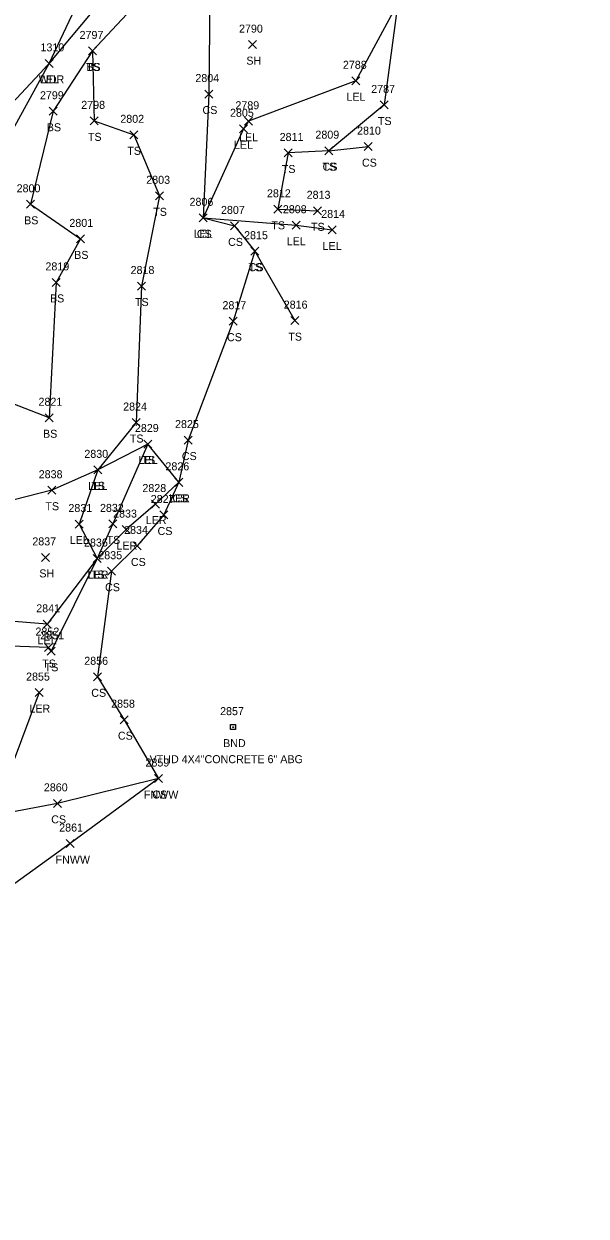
# Model space of a CAD drawing. Extents: x 1483143 to 1488182, y 802902 to 807581.
# Drawn here: x 1487452.4 to 1487593, y 805194.3 to 805492.2 of the extents above; entities that cross this region are included whole.
import ezdxf

# ---------------------------------------------------------------- set-up
doc = ezdxf.new("R2010")
doc.units = 0
for name, color, linetype in [('L_A', 7, 'Continuous'), ('L_I', 7, 'Continuous'), ('L_TIC', 7, 'Continuous'), ('LARO', 7, 'Continuous'), ('LAWA', 7, 'Continuous'), ('LELB', 7, 'Continuous'), ('LFNC', 7, 'Continuous'), ('M_A', 7, 'Continuous'), ('M_C', 7, 'Continuous'), ('M_I', 7, 'Continuous'), ('MHBP', 7, 'Continuous')]:
    doc.layers.add(name, color=color, linetype=linetype)

msp = doc.modelspace()

# ---------------------------------------------------------------- linework, layer by layer
at = {"layer": 'L_TIC'}
for points in [[(1487508.55, 805486.02), (1487510.55, 805488.02)], [(1487510.55, 805486.02), (1487508.55, 805488.02)], [(1487468.62, 805484.44), (1487470.62, 805486.44)], [(1487470.62, 805484.44), (1487468.62, 805486.44)], [(1487468.62, 805484.44), (1487470.62, 805486.44)], [(1487470.62, 805484.44), (1487468.62, 805486.44)], [(1487457.8, 805481.34), (1487459.8, 805483.34)], [(1487459.8, 805481.34), (1487457.8, 805483.34)], [(1487457.8, 805481.34), (1487459.8, 805483.34)], [(1487459.8, 805481.34), (1487457.8, 805483.34)], [(1487534.43, 805476.98), (1487536.43, 805478.98)], [(1487536.43, 805476.98), (1487534.43, 805478.98)], [(1487497.64, 805473.67), (1487499.64, 805475.67)], [(1487499.64, 805473.67), (1487497.64, 805475.67)], [(1487541.5, 805470.94), (1487543.5, 805472.94)], [(1487543.5, 805470.94), (1487541.5, 805472.94)], [(1487458.73, 805469.37), (1487460.73, 805471.37)], [(1487460.73, 805469.37), (1487458.73, 805471.37)], [(1487469.04, 805466.97), (1487471.04, 805468.97)], [(1487471.04, 805466.97), (1487469.04, 805468.97)], [(1487506.3, 805464.99), (1487508.3, 805466.99)], [(1487508.3, 805464.99), (1487506.3, 805466.99)], [(1487507.57, 805466.87), (1487509.57, 805468.87)], [(1487509.57, 805466.87), (1487507.57, 805468.87)], [(1487478.88, 805463.48), (1487480.88, 805465.48)], [(1487480.88, 805463.48), (1487478.88, 805465.48)], [(1487517.49, 805458.95), (1487519.49, 805460.95)], [(1487519.49, 805458.95), (1487517.49, 805460.95)], [(1487527.65, 805459.52), (1487529.65, 805461.52)], [(1487529.65, 805459.52), (1487527.65, 805461.52)], [(1487527.65, 805459.52), (1487529.65, 805461.52)], [(1487529.65, 805459.52), (1487527.65, 805461.52)], [(1487537.49, 805460.53), (1487539.49, 805462.53)], [(1487539.49, 805460.53), (1487537.49, 805462.53)], [(1487485.36, 805448.24), (1487487.36, 805450.24)], [(1487487.36, 805448.24), (1487485.36, 805450.24)], [(1487453.06, 805446.12), (1487455.06, 805448.12)], [(1487455.06, 805446.12), (1487453.06, 805448.12)], [(1487514.88, 805444.87), (1487516.88, 805446.87)], [(1487516.88, 805444.87), (1487514.88, 805446.87)], [(1487524.8, 805444.49), (1487526.8, 805446.49)], [(1487526.8, 805444.49), (1487524.8, 805446.49)], [(1487496.23, 805442.74), (1487498.23, 805444.74)], [(1487498.23, 805442.74), (1487496.23, 805444.74)], [(1487496.23, 805442.74), (1487498.23, 805444.74)], [(1487498.23, 805442.74), (1487496.23, 805444.74)], [(1487519.5, 805440.89), (1487521.5, 805442.89)], [(1487521.5, 805440.89), (1487519.5, 805442.89)], [(1487504.04, 805440.72), (1487506.04, 805442.72)], [(1487506.04, 805440.72), (1487504.04, 805442.72)], [(1487528.45, 805439.71), (1487530.45, 805441.71)], [(1487530.45, 805439.71), (1487528.45, 805441.71)], [(1487465.58, 805437.47), (1487467.58, 805439.47)], [(1487467.58, 805437.47), (1487465.58, 805439.47)], [(1487509.17, 805434.4), (1487511.17, 805436.4)], [(1487511.17, 805434.4), (1487509.17, 805436.4)], [(1487509.17, 805434.4), (1487511.17, 805436.4)], [(1487511.17, 805434.4), (1487509.17, 805436.4)], [(1487459.53, 805426.6), (1487461.53, 805428.6)], [(1487461.53, 805426.6), (1487459.53, 805428.6)], [(1487480.8, 805425.69), (1487482.8, 805427.69)], [(1487482.8, 805425.69), (1487480.8, 805427.69)], [(1487519.12, 805417.05), (1487521.12, 805419.05)], [(1487521.12, 805417.05), (1487519.12, 805419.05)], [(1487503.77, 805416.91), (1487505.77, 805418.91)], [(1487505.77, 805416.91), (1487503.77, 805418.91)], [(1487457.79, 805392.78), (1487459.79, 805394.78)], [(1487459.79, 805392.78), (1487457.79, 805394.78)], [(1487479.51, 805391.58), (1487481.51, 805393.58)], [(1487481.51, 805391.58), (1487479.51, 805393.58)], [(1487492.48, 805387.2), (1487494.48, 805389.2)], [(1487494.48, 805387.2), (1487492.48, 805389.2)], [(1487482.45, 805386.21), (1487484.45, 805388.21)], [(1487484.45, 805386.21), (1487482.45, 805388.21)], [(1487482.45, 805386.21), (1487484.45, 805388.21)], [(1487484.45, 805386.21), (1487482.45, 805388.21)], [(1487469.89, 805379.76), (1487471.89, 805381.76)], [(1487471.89, 805379.76), (1487469.89, 805381.76)], [(1487469.89, 805379.76), (1487471.89, 805381.76)], [(1487471.89, 805379.76), (1487469.89, 805381.76)], [(1487490.14, 805376.64), (1487492.14, 805378.64)], [(1487492.14, 805376.64), (1487490.14, 805378.64)], [(1487490.14, 805376.64), (1487492.14, 805378.64)], [(1487492.14, 805376.64), (1487490.14, 805378.64)], [(1487490.14, 805376.64), (1487492.14, 805378.64)], [(1487492.14, 805376.64), (1487490.14, 805378.64)], [(1487458.41, 805374.67), (1487460.41, 805376.67)], [(1487460.41, 805374.67), (1487458.41, 805376.67)], [(1487484.32, 805371.21), (1487486.32, 805373.21)], [(1487486.32, 805371.21), (1487484.32, 805373.21)], [(1487486.41, 805368.48), (1487488.41, 805370.48)], [(1487488.41, 805368.48), (1487486.41, 805370.48)], [(1487465.26, 805366.22), (1487467.26, 805368.22)], [(1487467.26, 805366.22), (1487465.26, 805368.22)], [(1487473.71, 805366.25), (1487475.71, 805368.25)], [(1487475.71, 805366.25), (1487473.71, 805368.25)], [(1487477, 805364.83), (1487479, 805366.83)], [(1487479, 805364.83), (1487477, 805366.83)], [(1487479.75, 805360.74), (1487481.75, 805362.74)], [(1487481.75, 805360.74), (1487479.75, 805362.74)], [(1487456.81, 805357.88), (1487458.81, 805359.88)], [(1487458.81, 805357.88), (1487456.81, 805359.88)], [(1487469.78, 805357.6), (1487471.78, 805359.6)], [(1487471.78, 805357.6), (1487469.78, 805359.6)], [(1487469.78, 805357.6), (1487471.78, 805359.6)], [(1487471.78, 805357.6), (1487469.78, 805359.6)], [(1487469.78, 805357.6), (1487471.78, 805359.6)], [(1487471.78, 805357.6), (1487469.78, 805359.6)], [(1487473.3, 805354.43), (1487475.3, 805356.43)], [(1487475.3, 805354.43), (1487473.3, 805356.43)], [(1487457.23, 805341.16), (1487459.23, 805343.16)], [(1487459.23, 805341.16), (1487457.23, 805343.16)], [(1487457.6, 805335.35), (1487459.6, 805337.35)], [(1487459.6, 805335.35), (1487457.6, 805337.35)], [(1487458.23, 805334.43), (1487460.23, 805336.43)], [(1487460.23, 805334.43), (1487458.23, 805336.43)], [(1487469.84, 805328.04), (1487471.84, 805330.04)], [(1487471.84, 805328.04), (1487469.84, 805330.04)], [(1487455.25, 805324.1), (1487457.25, 805326.1)], [(1487457.25, 805324.1), (1487455.25, 805326.1)], [(1487476.5, 805317.33), (1487478.5, 805319.33)], [(1487478.5, 805317.33), (1487476.5, 805319.33)], [(1487485.09, 805302.62), (1487487.09, 805304.62)], [(1487487.09, 805302.62), (1487485.09, 805304.62)], [(1487485.09, 805302.62), (1487487.09, 805304.62)], [(1487487.09, 805302.62), (1487485.09, 805304.62)], [(1487459.83, 805296.42), (1487461.83, 805298.42)], [(1487461.83, 805296.42), (1487459.83, 805298.42)], [(1487463.01, 805286.37), (1487465.01, 805288.37)], [(1487465.01, 805286.37), (1487463.01, 805288.37)]]:
    msp.add_lwpolyline(points, dxfattribs=at)
at = {"layer": 'LARO'}
for points in [[(1487588.58, 805526.63), (1487590.59, 805545), (1487592.96, 805554.51), (1487586.37, 805555.29), (1487579.73, 805548.18), (1487566.49, 805524.58), (1487556.52, 805508.05), (1487545.89, 805497.41), (1487535.43, 805477.98), (1487508.57, 805467.87), (1487507.3, 805465.99), (1487497.23, 805443.74), (1487520.5, 805441.89), (1487529.45, 805440.71)], [(1487275.82, 805186.86), (1487281.82, 805201.01), (1487291.77, 805208.89), (1487296.21, 805220.88), (1487297.4, 805236.19), (1487306.61, 805244.48), (1487316.03, 805247.44), (1487325.53, 805270.19), (1487336.29, 805289.62), (1487349.28, 805303.76), (1487363.04, 805323.38), (1487373.75, 805338.95), (1487382.28, 805358.58), (1487388.76, 805365.45), (1487390.53, 805372.85), (1487405.19, 805401.03), (1487414.25, 805416.49), (1487427.8, 805437.51), (1487440.02, 805462.35), (1487458.8, 805482.34), (1487468.72, 805503.53)], [(1487491.14, 805377.64), (1487483.45, 805387.21), (1487470.89, 805380.76), (1487466.26, 805367.22), (1487470.78, 805358.6), (1487458.23, 805342.16), (1487444.75, 805343.28), (1487439.56, 805348.1), (1487434.38, 805355.52), (1487412.49, 805358.06), (1487395.27, 805335), (1487373.89, 805314.55), (1487364.88, 805297.34), (1487361.7, 805278.72), (1487355.69, 805264.09), (1487356.67, 805249.84), (1487363.34, 805255.29)], [(1487491.14, 805377.64), (1487485.32, 805372.21), (1487478, 805365.83), (1487470.78, 805358.6)], [(1487456.25, 805325.1), (1487449.49, 805307.02), (1487440.44, 805293.54), (1487432.38, 805303.06), (1487424.19, 805296.14), (1487419.05, 805278.13), (1487404.37, 805277), (1487399.34, 805296.74), (1487390.95, 805305.22), (1487381.16, 805310.21), (1487373.89, 805314.55), (1487369.31, 805297.84), (1487368.9, 805261.33), (1487363.34, 805255.29)]]:
    msp.add_lwpolyline(points, dxfattribs=at)
at = {"layer": 'LAWA'}
msp.add_lwpolyline([(1487288.55, 805192.53), (1487294.52, 805206.51), (1487300.85, 805219.32), (1487309.39, 805232.65), (1487323.83, 805245.51), (1487330.77, 805260.07), (1487338.78, 805272.82), (1487344.77, 805283.02), (1487356.05, 805303.3), (1487368.2, 805318.3), (1487378.28, 805337.62), (1487391.65, 805357.45), (1487395.2, 805367.59), (1487402.1, 805377.95), (1487420, 805408.55), (1487434.6, 805433.13), (1487446.38, 805459.81), (1487458.8, 805482.34), (1487472.47, 805498.82)], dxfattribs=at)
at = {"layer": 'LELB'}
for points in [[(1487494, 805544.66), (1487489.98, 805516.76), (1487483.1, 805499.99), (1487469.62, 805485.44), (1487459.73, 805470.37), (1487454.06, 805447.12), (1487466.58, 805438.47), (1487460.53, 805427.6), (1487458.79, 805393.78), (1487437.28, 805402.12), (1487422.27, 805383.88)], [(1487498.95, 805499.29), (1487498.64, 805474.67), (1487497.23, 805443.74), (1487505.04, 805441.72), (1487510.17, 805435.4), (1487504.77, 805417.91), (1487493.48, 805388.2), (1487491.14, 805377.64), (1487487.41, 805369.48), (1487480.75, 805361.74), (1487474.3, 805355.43), (1487470.84, 805329.04), (1487477.5, 805318.33), (1487486.09, 805303.62), (1487460.83, 805297.42), (1487440.44, 805293.54)], [(1487545.89, 805497.41), (1487542.5, 805471.94), (1487528.65, 805460.52), (1487518.49, 805459.95), (1487515.88, 805445.87), (1487525.8, 805445.49)], [(1487469.62, 805485.44), (1487470.04, 805467.97), (1487479.88, 805464.48), (1487486.36, 805449.24), (1487481.8, 805426.69), (1487480.51, 805392.58), (1487470.89, 805380.76), (1487459.41, 805375.67), (1487434.38, 805369.29), (1487418.5, 805371.32), (1487412.49, 805358.06), (1487412.19, 805330.45), (1487418.38, 805300.5)], [(1487528.65, 805460.52), (1487538.49, 805461.53)], [(1487510.17, 805435.4), (1487520.12, 805418.05)], [(1487483.45, 805387.21), (1487474.71, 805367.25), (1487470.78, 805358.6), (1487459.23, 805335.43), (1487458.6, 805336.35), (1487444.36, 805336.9), (1487444.72, 805321.3), (1487438.81, 805304.38), (1487432.38, 805303.06), (1487428.45, 805308.43), (1487418.38, 805300.5)]]:
    msp.add_lwpolyline(points, dxfattribs=at)
at = {"layer": 'LFNC'}
msp.add_lwpolyline([(1487486.09, 805303.62), (1487464.01, 805287.37), (1487426.01, 805259.99), (1487401.42, 805242.52), (1487400.19, 805241.82), (1487381.81, 805228.11), (1487374.75, 805223.04), (1487372.52, 805220.64), (1487362.23, 805213.48), (1487358.33, 805209.86), (1487353.9, 805206.31), (1487340.39, 805197.17), (1487324.4, 805185.57), (1487312.71, 805164.9), (1487301.18, 805144.21), (1487298.04, 805137.83), (1487294.36, 805131.51), (1487284.56, 805115.26), (1487273.31, 805094.59), (1487256.78, 805068.37), (1487246.92, 805049.65), (1487232.59, 805026.14), (1487217.26, 805000.45), (1487203.24, 804976.05)], dxfattribs=at)
at = {"layer": 'MHBP'}
msp.add_lwpolyline([(1487504.11, 805317.09), (1487505.36, 805317.09), (1487505.36, 805315.84), (1487504.11, 805315.84)], close=True, dxfattribs=at)
msp.add_circle((1487504.74, 805316.46), 0.0833, dxfattribs=at)

# ---------------------------------------------------------------- texts
at = {"layer": 'L_A'}
for s, p in [('TS', (1487468.03, 805480.44)), ('BS', (1487468.06, 805480.44)), ('SH', (1487508.04, 805482.02)), ('WDR', (1487456.16, 805477.34)), ('LEL', (1487456.44, 805477.34)), ('LEL', (1487533.06, 805472.98)), ('CS', (1487497.08, 805469.67)), ('BS', (1487458.17, 805465.37)), ('TS', (1487540.91, 805466.94)), ('TS', (1487468.45, 805462.97)), ('LEL', (1487506.21, 805462.87)), ('TS', (1487478.29, 805459.48)), ('LEL', (1487504.94, 805460.99)), ('CS', (1487536.93, 805456.53)), ('TS', (1487516.9, 805454.95)), ('TS', (1487527.06, 805455.52)), ('CS', (1487527.09, 805455.52)), ('TS', (1487484.77, 805444.24)), ('BS', (1487452.5, 805442.12)), ('TS', (1487514.29, 805440.87)), ('LEL', (1487494.87, 805438.74)), ('CS', (1487495.67, 805438.74)), ('TS', (1487524.21, 805440.49)), ('CS', (1487503.48, 805436.72)), ('LEL', (1487518.13, 805436.89)), ('LEL', (1487527.08, 805435.71)), ('BS', (1487465.02, 805433.47)), ('TS', (1487508.57, 805430.4)), ('CS', (1487508.61, 805430.4)), ('BS', (1487458.97, 805422.6)), ('TS', (1487480.21, 805421.69)), ('CS', (1487503.21, 805412.91)), ('TS', (1487518.53, 805413.05)), ('BS', (1487457.23, 805388.78)), ('TS', (1487478.92, 805387.58)), ('LEL', (1487481.09, 805382.21)), ('TS', (1487481.86, 805382.21)), ('CS', (1487491.92, 805383.2)), ('LEL', (1487468.53, 805375.76)), ('TS', (1487469.3, 805375.76)), ('LER', (1487488.72, 805372.64)), ('LEL', (1487488.78, 805372.64)), ('CS', (1487489.58, 805372.64)), ('TS', (1487457.82, 805370.67)), ('LER', (1487482.91, 805367.21)), ('CS', (1487485.85, 805364.48)), ('LEL', (1487463.9, 805362.22)), ('TS', (1487473.12, 805362.25)), ('LER', (1487475.58, 805360.83)), ('CS', (1487479.19, 805356.74)), ('SH', (1487456.3, 805353.88)), ('LER', (1487468.37, 805353.6)), ('LEL', (1487468.42, 805353.6)), ('TS', (1487469.19, 805353.6)), ('CS', (1487472.74, 805350.43)), ('LEL', (1487455.86, 805337.16)), ('TS', (1487457.01, 805331.35)), ('TS', (1487457.64, 805330.43)), ('CS', (1487469.28, 805324.04)), ('LER', (1487453.83, 805320.1)), ('CS', (1487475.94, 805313.33)), ('FNWW', (1487482.44, 805298.62)), ('CS', (1487484.53, 805298.62)), ('CS', (1487459.27, 805292.42)), ('FNWW', (1487460.36, 805282.37))]:
    msp.add_text(s, height=2, dxfattribs=at).set_placement(p)
at = {"layer": 'L_I'}
for s, p in [('2797', (1487466.36, 805488.44)), ('2797', (1487466.36, 805488.44)), ('2790', (1487506.21, 805490.02)), ('1310', (1487456.59, 805485.34)), ('1310', (1487456.59, 805485.34)), ('2788', (1487532.17, 805480.98)), ('2804', (1487495.3, 805477.67)), ('2787', (1487539.24, 805474.94)), ('2799', (1487456.46, 805473.37)), ('2798', (1487466.78, 805470.97)), ('2789', (1487505.3, 805470.87)), ('2805', (1487503.96, 805468.99)), ('2802', (1487476.54, 805467.48)), ('2811', (1487516.36, 805462.95)), ('2809', (1487525.3, 805463.52)), ('2809', (1487525.3, 805463.52)), ('2810', (1487535.71, 805464.53)), ('2800', (1487450.63, 805450.12)), ('2803', (1487483.02, 805452.24)), ('2806', (1487493.84, 805446.74)), ('2806', (1487493.84, 805446.74)), ('2812', (1487513.19, 805448.87)), ('2813', (1487523.11, 805448.49)), ('2807', (1487501.7, 805444.72)), ('2808', (1487517.16, 805444.89)), ('2801', (1487463.81, 805441.47)), ('2814', (1487526.75, 805443.71)), ('2815', (1487507.47, 805438.4)), ('2815', (1487507.47, 805438.4)), ('2819', (1487457.83, 805430.6)), ('2818', (1487479.11, 805429.69)), ('2817', (1487502.07, 805420.91)), ('2816', (1487517.38, 805421.05)), ('2821', (1487456.1, 805396.78)), ('2824', (1487477.25, 805395.58)), ('2829', (1487480.19, 805390.21)), ('2829', (1487480.19, 805390.21)), ('2825', (1487490.22, 805391.2)), ('2830', (1487467.55, 805383.76)), ('2830', (1487467.55, 805383.76)), ('2838', (1487456.15, 805378.67)), ('2826', (1487487.82, 805380.64)), ('2826', (1487487.82, 805380.64)), ('2826', (1487487.82, 805380.64)), ('2828', (1487482.06, 805375.21)), ('2827', (1487484.15, 805372.48)), ('2831', (1487463.57, 805370.22)), ('2832', (1487471.46, 805370.25)), ('2833', (1487474.74, 805368.83)), ('2834', (1487477.49, 805364.74)), ('2837', (1487454.55, 805361.88)), ('2836', (1487467.47, 805361.6)), ('2836', (1487467.47, 805361.6)), ('2836', (1487467.47, 805361.6)), ('2835', (1487471.04, 805358.43)), ('2841', (1487455.53, 805345.16)), ('2852', (1487455.34, 805339.35)), ('2851', (1487456.54, 805338.43)), ('2856', (1487467.53, 805332.04)), ('2855', (1487452.99, 805328.1)), ('2858', (1487474.24, 805321.33)), ('2859', (1487482.83, 805306.62)), ('2859', (1487482.83, 805306.62)), ('2860', (1487457.44, 805300.42)), ('2861', (1487461.27, 805290.37))]:
    msp.add_text(s, height=2, dxfattribs=at).set_placement(p)
at = {"layer": 'M_A'}
msp.add_text('BND', height=2, dxfattribs=at).set_placement((1487502.23, 805311.46))
at = {"layer": 'M_C'}
msp.add_text('VTHD 4X4"CONCRETE 6" ABG', height=2, dxfattribs=at).set_placement((1487483.86, 805307.46))
at = {"layer": 'M_I'}
msp.add_text('2857', height=2, dxfattribs=at).set_placement((1487501.48, 805319.46))

doc.saveas('drawing.dxf')
